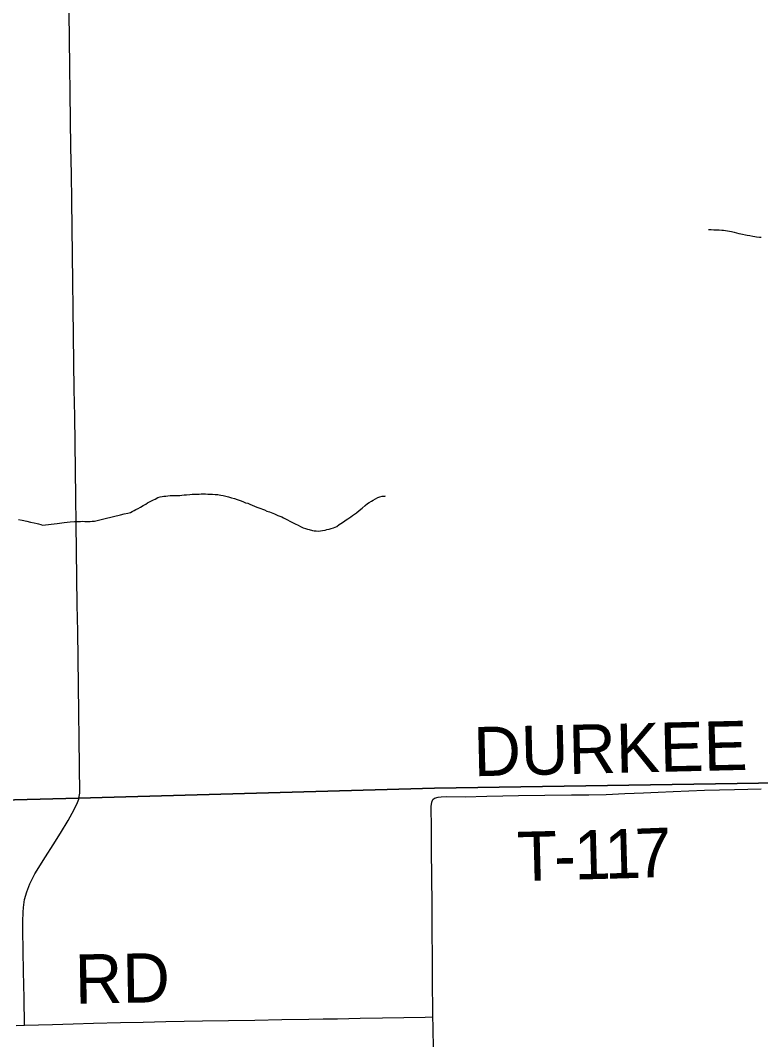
# Model space of a CAD drawing. Extents: x 103424 to 290657, y 38711 to 110967.
# Drawn here: x 166595 to 171137, y 70588 to 76839 of the extents above; entities that cross this region are included whole.
import ezdxf

# ---------------------------------------------------------------- set-up
doc = ezdxf.new("R2010")
doc.units = 0
for name, color, linetype in [('GM_X_Corporation', 7, 'Continuous'), ('GM_X_County_Road', 7, 'Continuous'), ('GM_X_County_Road_Text', 7, 'Continuous'), ('GM_X_Minor_River', 7, 'Continuous'), ('GM_X_Township_Road', 7, 'Continuous'), ('GM_X_Township_Road_Text', 7, 'Continuous')]:
    doc.layers.add(name, color=color, linetype=linetype)

msp = doc.modelspace()

# ---------------------------------------------------------------- linework, layer by layer
at = {"layer": 'GM_X_Corporation'}
for points in [[(148594.2, 97294.7), (158050.5, 97608.1), (158064.2, 97608.5), (162306.4, 97749.1), (162479.3, 97753.8), (165116.9, 97825.6), (173478.4, 98058.2), (173550.7, 94746.5), (173649.8, 90059.6), (173693.6, 87690.3), (173775.2, 84514.7), (174054.1, 73155.3), (174066.9, 72315.5), (174070.5, 72208.9), (173777.3, 72202), (169136.7, 72130.4), (166950.9, 72068.3), (161596.3, 71930.5), (161287.7, 71923.7), (157064.3, 71829.7), (151578, 71707.7), (149073.5, 71652)], [(149073.5, 71652), (151578, 71707.7), (157064.3, 71829.7), (161287.7, 71923.7), (161596.3, 71930.5), (166950.9, 72068.3), (169136.7, 72130.4), (173777.3, 72202), (174070.5, 72208.9), (174125.3, 69464.1), (174128.9, 69223), (174137.2, 68978.3), (174140.8, 68790.7), (174153.5, 68330.8), (174162.2, 67903.5), (174163.3, 67850.7), (174375.3, 58453.3)]]:
    msp.add_lwpolyline(points, dxfattribs=at)
at = {"layer": 'GM_X_County_Road'}
for points in [[(166568.6, 70675.1), (166620.6, 70676.4), (166706.2, 70678.5), (166791.8, 70680.5), (166917.5, 70684.3), (167043.2, 70688.1), (167208.2, 70692), (167347.9, 70695.3), (167487.6, 70698.6), (167599.5, 70701), (167711.4, 70703.5), (167872.5, 70705.4), (168033.6, 70707.4), (168198.6, 70710.3), (168363.7, 70713.2), (168451.7, 70714.7), (168539.6, 70716.3), (168678.7, 70718.6), (168817.7, 70720.9), (168948.4, 70723.6), (169079.1, 70726.2), (169126.1, 70727)], [(169129.9, 70522.8), (169128.3, 70665.5), (169126.1, 70727)]]:
    msp.add_lwpolyline(points, dxfattribs=at)
at = {"layer": 'GM_X_Minor_River'}
for points in [[(170817.4, 75555.3), (170833.6, 75555.3), (170849.8, 75553.4), (170865.9, 75553.5), (170882.1, 75553.6), (170898.2, 75551.6), (170908.3, 75551.7), (170922.5, 75549.7), (170934.6, 75547.7), (170946.8, 75545.8), (170958.9, 75543.8), (170975.1, 75539.9), (170989.2, 75535.9), (171003.4, 75531.9), (171015.5, 75530), (171025.6, 75528), (171043.8, 75524), (171054, 75522.1), (171070.1, 75520.1), (171088.3, 75516.2), (171102.5, 75514.2), (171112.6, 75512.2), (171130.8, 75510.3), (171140.9, 75508.3)], [(167115.4, 73784.2), (167208.1, 73806.4), (167232.3, 73812.6), (167254.5, 73816.7), (167270.7, 73820.8), (167280.7, 73826.9), (167292.8, 73833.1), (167302.9, 73839.2), (167317, 73845.3), (167331.1, 73853.5), (167347.2, 73863.7), (167365.3, 73871.8), (167375.3, 73880), (167411.6, 73898.4), (167421.7, 73902.5), (167437.8, 73912.7), (167451.9, 73916.8), (167464, 73918.8), (167474.1, 73920.9), (167486.2, 73921), (167500.3, 73923.1), (167514.4, 73925.2), (167530.6, 73925.2), (167544.7, 73925.3), (167558.9, 73925.4), (167573, 73925.5), (167585.1, 73927.5), (167599.3, 73929.6), (167613.4, 73929.7), (167633.6, 73931.8), (167649.7, 73933.9), (167665.9, 73934), (167680, 73934.1), (167692.2, 73934.1), (167704.3, 73934.2), (167718.4, 73934.3), (167730.5, 73934.3), (167744.7, 73932.4), (167758.8, 73932.4), (167773, 73932.5), (167789.1, 73930.6), (167805.3, 73930.7), (167815.4, 73928.7), (167825.5, 73926.7), (167839.7, 73924.7), (167855.9, 73920.8), (167872, 73916.8), (167890.3, 73910.8), (167908.5, 73906.9), (167924.7, 73900.9), (167936.8, 73896.9), (167949, 73892.9), (167963.1, 73886.9), (167975.3, 73880.9), (167989.5, 73877), (168003.6, 73871), (168017.8, 73865), (168032, 73859), (168046.2, 73853), (168058.3, 73849), (168092.7, 73837), (168106.9, 73829), (168123.1, 73825), (168133.2, 73821), (168143.3, 73817), (168153.5, 73813.1), (168173.7, 73803), (168185.9, 73799.1), (168200, 73793.1), (168210.2, 73787.1), (168222.3, 73781), (168234.5, 73775), (168248.7, 73767), (168260.8, 73761), (168273, 73755), (168285.2, 73749), (168295.3, 73745), (168317.6, 73733), (168329.7, 73727), (168343.9, 73723), (168356, 73719), (168366.1, 73717), (168386.4, 73711.1), (168396.5, 73709.1), (168410.6, 73709.2), (168424.8, 73707.2), (168436.9, 73707.3), (168449, 73709.4), (168465.2, 73711.5), (168475.2, 73715.5), (168489.4, 73717.6), (168501.5, 73721.7), (168515.6, 73725.9), (168525.7, 73729.9), (168535.7, 73734), (168551.8, 73746.3), (168561.9, 73752.4), (168578, 73762.6), (168594.1, 73774.8)], [(168594.1, 73774.8), (168604.1, 73780.9), (168622.2, 73795.1), (168632.3, 73803.3), (168656.4, 73819.6), (168674.5, 73833.8), (168692.6, 73848.1), (168710.7, 73864.3), (168724.7, 73876.5), (168734.8, 73882.7), (168748.9, 73890.8), (168759, 73896.9), (168773, 73905.1), (168787.1, 73913.2), (168801.3, 73917.4), (168815.4, 73921.5), (168831.5, 73921.6), (168835.6, 73923.6)], [(166583.3, 73777.8), (166605.6, 73774.1), (166633.9, 73766.6), (166656.2, 73760.9), (166678.5, 73757.2), (166696.7, 73753.5), (166706.8, 73751.7), (166721, 73747.9), (166731.2, 73744), (166819.8, 73753.7), (166864.1, 73758.5), (166900.3, 73763.2), (166926.5, 73765.7), (166942.7, 73766), (166952.8, 73766.2), (166962.8, 73766.4), (166975, 73766.6), (166989.1, 73764.8), (167003.2, 73765.1), (167023.4, 73765.4), (167035.5, 73767.7), (167049.6, 73767.9), (167115.4, 73784.2)]]:
    msp.add_lwpolyline(points, dxfattribs=at)
at = {"layer": 'GM_X_Township_Road'}
msp.add_line((166952.4, 72063.2), (166954.3, 72068.3), dxfattribs=at)
for points in [[(166954.3, 72068.3), (166960, 72099.9), (166957.8, 72265), (166955.5, 72430), (166953.2, 72595.1), (166950.9, 72760.2), (166948.6, 72925.2), (166946.3, 73090.3), (166944, 73255.4), (166941.7, 73420.4), (166939.4, 73585.5), (166937.1, 73750.6), (166934.8, 73915.6), (166932.5, 74080.7), (166930.2, 74245.7), (166927.9, 74410.8), (166925.6, 74575.9), (166923.4, 74740.9), (166921, 74906), (166918.7, 75071.1), (166916.5, 75236.1), (166914.1, 75401.2), (166911.9, 75566.3), (166909.6, 75731.3), (166907.3, 75896.4), (166905, 76061.5), (166902.7, 76226.5), (166900.4, 76391.6), (166898.1, 76556.7), (166895.8, 76721.7), (166893.5, 76886.8)], [(169135, 72068), (169157.5, 72075.2), (169176.8, 72077.7), (169207.7, 72079.6), (169324.1, 72077.3), (169457.5, 72080.9), (169554.2, 72082.9), (169650.9, 72084.8), (169813.7, 72087), (169976.5, 72089.2), (170082.6, 72089.7), (170188.8, 72090.3), (170303.9, 72097.4), (170417.6, 72101.1), (170509.3, 72105.2), (170600.9, 72109.2), (170696.4, 72113.7), (170791.8, 72118.2), (170883.8, 72119.8), (170975.8, 72121.4), (171058.6, 72123.4), (171141.3, 72125.4)], [(166620.6, 70676.4), (166617.4, 70841.5), (166614.2, 71006.5), (166611.7, 71132.7), (166609.3, 71258.8), (166608.9, 71313.2), (166610.8, 71369.7), (166613, 71398.3), (166620.5, 71447.1), (166634.9, 71493.9), (166653.6, 71543.8), (166684.1, 71605.6), (166749.2, 71709.4), (166795.3, 71781.7), (166841.4, 71854.1), (166887.9, 71931.8), (166925.5, 71999.2), (166944.8, 72042.7), (166952.4, 72063.2)], [(169126.1, 70727), (169125.4, 70769.9), (169124.1, 70929.4), (169122.9, 71088.9), (169121.8, 71253.9), (169120.6, 71419), (169119.4, 71584.1), (169118.3, 71749.1), (169117.4, 71883.5), (169116.4, 72017.8), (169120.2, 72044.8), (169126.6, 72059.7), (169135, 72068)]]:
    msp.add_lwpolyline(points, dxfattribs=at)

# ---------------------------------------------------------------- texts
at = {"layer": 'GM_X_County_Road_Text'}
msp.add_text('RD', height=301.87, rotation=0.98737, dxfattribs=at).set_placement((166931.1, 70808.1))
at = {"layer": 'GM_X_Township_Road_Text'}
for s, height, rotation, p in [('DURKEE', 301.87, 1.35717, (169378, 72202.7)), ('7', 301.9, 2.15439, (170371.7, 71579.3)), ('T', 301.9, 1.4487, (169646.2, 71560.1)), ('1', 301.9, 1.49698, (169996.1, 71569)), ('1', 301.9, 1.63887, (170182.8, 71573.9)), ('-', 301.9, 1.45725, (169872, 71565.8))]:
    msp.add_text(s, height=height, rotation=rotation, dxfattribs=at).set_placement(p)

doc.saveas('drawing.dxf')
